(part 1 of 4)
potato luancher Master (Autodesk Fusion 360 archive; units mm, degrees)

design "potato luancher" references "Broached Hexagon Socket Head Cap Screw ANSI B18.3.1M - M3x0.5 x 25 Steel Grade 2 Zinc", "Socket Head Cap Screw JIS B 1176 - M3 x 0.5 x 20 Steel 4.6 Plain", "Hexagon Socket Head Cap Screw ANSI B18.3 - 1/4-28 UNF x 0.75 Steel Grade 2 Plain"
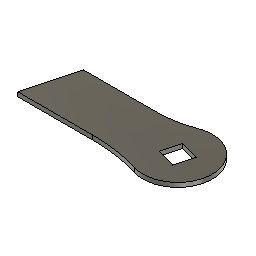
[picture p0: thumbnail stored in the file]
parameter "valveShaftHoleSzOffset" = 0.3
parameter "camInnerDiameter" = 80.9625 (= "3.1875 * 1 in")
parameter "big_nut" = 11.8872
parameter "d3" = 2.5
parameter "d71" = 3.175 (= "( 1 / 8 ) * 1 in")
parameter "d88" = 1.5189
parameter "d205" = 6.35
parameter "d237" = 2
parameter "d459" = 152.4
sketch "valve profile" plane through (0, 0, 0) normal (0, 1, 0) x axis (1, 0, 0)
canvas "Canvas1"
sketch "tank profile" plane through (0, 0, 0) normal (1, 0, 0) x axis (0, 1, 0)
  line L1 (0, 24.13) -> (-37.338, 24.13)
  line L2 (0, -24.13) -> (0, 24.13)
  line L3 (-37.338, -24.13) -> (0, -24.13)
  line L4 (-37.338, 24.13) -> (-37.338, -24.13)
  line L5 (146.556, 88.9) -> (44.956, 88.9)
  line L6 (146.556, -88.9) -> (146.556, 88.9)
  line L7 (44.956, -88.9) -> (146.556, -88.9)
  line L8 (44.956, 88.9) -> (44.956, -88.9)
  line L9 (-86.3742, 0) -> (44.956, 0)
  line L10 (146.556, 0) -> (-37.338, 0)
  arc A1 centre (69.1365, 24.13) radius 69.1365 clockwise from (0, 24.13) to (44.956, 88.9)
  arc A2 centre (69.1365, -24.13) radius 69.1365 clockwise from (44.956, -88.9) to (0, -24.13)
  point P11 (44.956, 0)
  point P13 (0, 0)
  point P3 (0, 24.13)
  point P16 (0, -24.13)
  point P6 (44.956, 88.9)
  point P15 (44.956, -88.9)
  point P17 (0, 0)
  point P18 (-37.338, 0)
  point P19 (146.556, 0)
  point P2 (-37.338, 24.13)
  point P5 (-37.338, -24.13)
  point P8 (146.556, 88.9)
  point P9 (146.556, -88.9)
  horizontal L1
  vertical L2
  horizontal L3
  vertical L4
  horizontal L5
  vertical L6
  horizontal L7
  vertical L8
  midpoint L8 P11
  perpendicular L8 L9
  midpoint L2 P13
  coincident L9 P13
  tangent L2 A1
  symmetric P3 L9 P16
  symmetric P6 L9 P15
  symmetric A1 L9 A2
  coincident P13 P17
  midpoint L4 P18
  midpoint L6 P19
  dimension "d4" distance P2 P5 = 48.26
  dimension "d5" distance P2 P3 = 37.338
  dimension "d6" distance P8 P9 = 177.8
  dimension "d7" distance P6 P8 = 101.6
  dimension "d8" distance L2 L8 = 44.956
  dimension "d320" AlongDistance = 263.274
  dimension "d458" diameter = 19.05
revolve "Revolve1" sketch "tank profile" AlongAngle 360
copy_paste_bodies "CutPasteBodies1"
sketch "Sketch1" plane through (0, 0, 0) normal (1, 0, 0) x axis (0, 1, 0)
  line L1 (-91.948, 28.067) -> (-77.216, 28.067)
  line L2 (-91.948, -28.067) -> (-91.948, 28.067)
  line L3 (-77.216, -28.067) -> (-91.948, -28.067)
  line L4 (-77.216, 28.067) -> (-77.216, -28.067)
  line L5 (-91.948, -28.067) -> (-77.216, 28.067)
  line L6 (-77.216, -28.067) -> (-91.948, 28.067)
  line L7 (-62.738, -31.115) -> (-28.702, -31.115)
  line L8 (-62.738, 31.115) -> (-62.738, -31.115)
  line L9 (-28.702, 31.115) -> (-62.738, 31.115)
  line L10 (-28.702, -31.115) -> (-28.702, 31.115)
  line L11 (-62.738, 31.115) -> (-28.702, -31.115)
  line L12 (-28.702, 31.115) -> (-62.738, -31.115)
  line L13 (-28.702, 32.385) -> (-14.224, 32.385)
  line L14 (-28.702, -32.385) -> (-28.702, 32.385)
  line L15 (-14.224, -32.385) -> (-28.702, -32.385)
  line L16 (-14.224, 32.385) -> (-14.224, -32.385)
  line L17 (-28.702, -32.385) -> (-14.224, 32.385)
  line L18 (-14.224, -32.385) -> (-28.702, 32.385)
  line L19 (-14.224, 27.9654) -> (0, 27.9654)
  line L20 (-14.224, -27.9654) -> (-14.224, 27.9654)
  line L21 (0, -27.9654) -> (-14.224, -27.9654)
  line L22 (0, 27.9654) -> (0, -27.9654)
  line L23 (-14.224, -27.9654) -> (0, 27.9654)
  line L24 (0, -27.9654) -> (-14.224, 27.9654)
  line L25 (27.6646, 0) -> (-172.9089, 0)
  arc A1 centre (-77.216, 63.9763) radius 35.9093 clockwise from (-62.738, 31.115) to (-77.216, 28.067)
  point P6 (-84.582, 0)
  point P11 (-45.72, 0)
  point P16 (-21.463, 0)
  point P21 (-7.112, 0)
  point P18 (-14.224, 27.9654)
  point P24 (0, 0)
  point P13 (-28.702, 32.385)
  point P1 (0, 0)
  point P2 (-77.216, 28.067)
  point P3 (-91.948, 28.067)
  point P9 (-62.738, 31.115)
  point P10 (-28.702, 31.115)
  point P12 (-14.224, 32.385)
  point P17 (0, 27.9654)
  point P4 (-91.948, -28.067)
  point P8 (-62.738, -31.115)
  point P14 (-28.702, -32.385)
  point P20 (0, -27.9654)
  horizontal L1
  perpendicular L1 L2
  parallel L1 L3
  parallel L2 L4
  coincident L5 P6
  coincident L6 P6
  horizontal L7
  perpendicular L7 L8
  parallel L7 L9
  parallel L8 L10
  coincident L11 P11
  coincident L12 P11
  horizontal L13
  perpendicular L13 L14
  parallel L13 L15
  parallel L14 L16
  coincident L17 P16
  coincident L18 P16
  horizontal L19
  perpendicular L19 L20
  parallel L19 L21
  parallel L20 L22
  coincident L23 P21
  coincident L24 P21
  coincident L16 P18
  perpendicular L2 L25
  coincident P6 L25
  coincident L25 P24
  coincident P11 L25
  coincident P16 L25
  coincident P21 L25
  coincident L10 P13
  coincident P1 L22
  tangent L1 A1
  dimension "d10" distance P2 P3 = 14.732
  dimension "d11" distance P9 P10 = 34.036
  dimension "d12" distance P12 P13 = 14.478
  dimension "d13" distance P17 P18 = 14.224
  dimension "d14" distance L2 L22 = 91.948
  dimension "d15" distance P3 P4 = 56.134
  dimension "d16" distance P8 P9 = 62.23
  dimension "d17" distance P13 P14 = 64.77
  dimension "d18" distance P17 P20 = 55.9308
revolve "Revolve1" sketch "Sketch1" AlongAngle 360
sketch "Sketch2" plane through (0, 0, 0) normal (1, 0, 0) x axis (0, 1, 0)
  line L1 (-33.782, 43.561) -> (-56.642, 43.561)
  line L2 (-33.782, 23.495) -> (-33.782, 43.561)
  line L3 (-56.642, 23.495) -> (-33.782, 23.495)
  line L4 (-56.642, 43.561) -> (-56.642, 23.495)
  line L5 (-62.738, 31.115) -> (-62.738, -31.115)
  line L6 (-28.702, 31.115) -> (-28.702, -31.115)
  line L7 (0, 27.9654) -> (0, -27.9654)
  line L8 (-62.738, 31.115) -> (-28.702, 31.115)
  line L9 (-45.212, 23.495) -> (-45.212, 43.561)
  line L10 (-45.212, 79.0444) -> (-45.212, 43.561)
  line L11 (-55.245, 43.561) -> (-35.179, 43.561)
  line L12 (-55.245, 47.117) -> (-55.245, 43.561)
  line L13 (-35.179, 47.117) -> (-55.245, 47.117)
  line L14 (-35.179, 43.561) -> (-35.179, 47.117)
  line L15 (-55.245, 47.117) -> (-35.179, 43.561)
  line L16 (-35.179, 47.117) -> (-55.245, 43.561)
  line L17 (-51.054, 47.117) -> (-39.37, 47.117)
  line L18 (-51.054, 58.547) -> (-51.054, 47.117)
  line L19 (-39.37, 58.547) -> (-51.054, 58.547)
  line L20 (-39.37, 47.117) -> (-39.37, 58.547)
  line L21 (-51.054, 58.547) -> (-39.37, 47.117)
  line L22 (-39.37, 58.547) -> (-51.054, 47.117)
  point P9 (-28.702, 31.115)
  point P12 (-28.702, 31.115)
  point P14 (-45.212, 43.561)
  point P15 (-45.212, 23.495)
  point P21 (-45.212, 45.339)
  point P17 (-35.179, 43.561)
  point P26 (-45.212, 52.832)
  point P22 (-39.37, 47.117)
  point P4 (-33.782, 23.495)
  point P2 (-56.642, 43.561)
  point P3 (-33.782, 43.561)
  point P19 (-55.245, 47.117)
  point P20 (-35.179, 47.117)
  point P24 (-51.054, 58.547)
  point P25 (-39.37, 58.547)
  horizontal L1
  vertical L2
  horizontal L3
  vertical L4
  coincident P9 P12
  perpendicular L5 L8
  midpoint L1 P14
  midpoint L3 P15
  perpendicular L1 L10
  horizontal L11
  perpendicular L11 L12
  parallel L11 L13
  parallel L12 L14
  coincident L15 P21
  coincident L16 P21
  coincident L10 P21
  coincident L1 P17
  horizontal L17
  perpendicular L17 L18
  parallel L17 L19
  parallel L18 L20
  coincident L21 P26
  coincident L22 P26
  coincident L10 P26
  coincident L13 P22
  dimension "d20" distance L2 L7 = 33.782
  dimension "d21" distance P4 L8 = 7.62
  dimension "d22" distance L1 L8 = 12.446
  dimension "d23" distance P2 P3 = 22.86
  dimension "d24" distance L1 L13 = 3.556
  dimension "d25" distance P19 P20 = 20.066
  dimension "d26" distance P24 P25 = 11.684
  dimension "d27" distance P22 P25 = 11.43
revolve "Revolve2" sketch "Sketch2" AlongAngle 360
sketch "Sketch3" plane through (0, 0, 58.547) normal (0, 0, 1) x axis (-1, 0, 0)
  line L1 (-3.429, 37.1067) -> (3.429, 37.1067)
  line L2 (-3.429, 53.3173) -> (-3.429, 37.1067)
  line L3 (3.429, 53.3173) -> (-3.429, 53.3173)
  line L4 (3.429, 37.1067) -> (3.429, 53.3173)
  line L5 (-3.429, 53.3173) -> (3.429, 37.1067)
  line L6 (3.429, 53.3173) -> (-3.429, 37.1067)
  circle C1 centre (0, 45.212) radius 5.842
  point P7 (0, 45.212)
  point P2 (0, 45.212)
  point P3 (3.429, 37.1067)
  point P6 (3.429, 53.3173)
  point P5 (-3.429, 53.3173)
  horizontal L1
  perpendicular L1 L2
  parallel L1 L3
  parallel L2 L4
  coincident L5 P7
  coincident L6 P7
  coincident P2 P7
  dimension "d29" distance P3 P6 = 16.2105
  dimension "d30" distance P5 P6 = 6.858
extrude "Extrude1" cut sketch "Sketch3" profile of C1 L2 L4 against normal blind 9.144
copy_paste_bodies "CutPasteBodies1"
sketch "Sketch1" plane through (0, 0, 49.403) normal (0, 0, 1) x axis (-1, 0, 0)
  line L1 (-3.429, 49.9418) -> (-3.429, 40.4822)
  line L2 (3.429, 49.9418) -> (3.429, 40.4822)
  line L3 (-3.429, 40.4822) -> (-3.429, 49.9418)
  line L4 (-10.795, 34.417) -> (10.795, 34.417)
  line L5 (-10.795, 56.007) -> (-10.795, 34.417)
  line L6 (10.795, 56.007) -> (-10.795, 56.007)
  line L7 (10.795, 34.417) -> (10.795, 56.007)
  line L8 (-10.795, 56.007) -> (10.795, 34.417)
  line L9 (10.795, 56.007) -> (-10.795, 34.417)
  arc A1 centre (0, 45.212) radius 5.842 clockwise from (-3.429, 40.4822) to (-3.429, 49.9418)
  arc A2 centre (0, 45.212) radius 5.842 clockwise from (-3.429, 49.9418) to (3.429, 49.9418)
  arc A3 centre (0, 45.212) radius 5.842 clockwise from (3.429, 40.4822) to (-3.429, 40.4822)
  circle C1 centre (0, 45.212) radius 10.795
  point P15 (0, 45.212)
  point P8 (0, 45.212)
  concentric A2 C1
  horizontal L4
  perpendicular L4 L5
  parallel L4 L6
  parallel L5 L7
  coincident L8 P15
  coincident L9 P15
  coincident P8 P15
  tangent C1 L7
  tangent C1 L4
  dimension "d33" diameter C1 = 21.59
extrude "Extrude1" new body sketch "Sketch1" profile of A1 L1 L2 A2 L3 A3 C1 L4 L5 L6 L7 along normal blind 3.175
copy_paste_bodies "CutPasteBodies1"
offset_faces "OffsetFaces1" distance 8.382 (= "-0.85 in + 1.18 in")
position "Position1"
as_built_joint "As-built1" OffsetX 0 OffsetY 0 OffsetZ 0 AngleZ 0
ground "Ground1"
work_plane "WorkPlane1" AlongDistance 44.958
extrude "Extrude1" add of existing geometry blind 330.2 (= "-4.00 in + 17 in")
sketch "plastic tank base" plane through (0, 476.756, 0) normal (0, 1, 0) x axis (-1, 0, 0)
  circle C1 centre (0, 0) radius 88.9
  circle C2 centre (0, 0) radius 90.4875
  concentric C1 C2
  dimension "d48" diameter C2 = 180.975
extrude "Extrude2" add sketch "plastic tank base" along normal blind 50.8
sketch "F handle shaft" plane through (0, 0, 0) normal (1, 0, 0) x axis (0, 1, 0)
  line L1 (70.356, 146.05) -> (83.056, 146.05)
  line L2 (70.356, 158.75) -> (70.356, 146.05)
  line L3 (83.056, 158.75) -> (70.356, 158.75)
  line L4 (83.056, 146.05) -> (83.056, 158.75)
  line L5 (70.356, 158.75) -> (83.056, 146.05)
  line L6 (83.056, 158.75) -> (70.356, 146.05)
  point P6 (76.706, 152.4)
  point P4 (70.356, 158.75)
  point P5 (83.056, 158.75)
  point P3 (70.356, 146.05)
  point P7 (44.956, 88.9)
  horizontal L1
  perpendicular L1 L2
  parallel L1 L3
  parallel L2 L4
  coincident L5 P6
  coincident L6 P6
  dimension "d51" distance P4 P5 = 12.7
  dimension "d52" distance P3 P4 = 12.7
  dimension "d53" distance P6 P7 = 63.5
  dimension "d54" distance P6 P7 = 31.75
extrude "Extrude1" new body sketch "F handle shaft" profile of L1 L2 L3 L4 distance 133.35
work_plane "WorkPlane3" AlongDistance -6.35 (= "-0.50 in / 2")
sketch "Sketch11" plane through (0, 76.706, 0) normal (0, -1, 0) x axis (-1, 0, 0)
  line L1 (-66.675, -146.05) -> (-66.675, -158.75)
  line L2 (-66.675, -158.75) -> (-66.675, -146.05)
  line L3 (-66.675, -146.05) -> (66.675, -146.05)
  line L4 (-66.675, -158.75) -> (-66.675, -146.05)
  line L5 (66.675, -158.75) -> (-66.675, -158.75)
  line L6 (66.675, -146.05) -> (66.675, -158.75)
  line L7 (-63.5, -62.217) -> (-63.5, -146.05)
  circle C1 centre (0, 0) radius 88.9
  circle C2 centre (0, 0) radius 88.9
  point P9 (-63.5, -146.05)
  point P10 (-63.5, -62.217)
  point P4 (-66.675, -146.05)
  coincident L3 P9
  vertical L7
  coincident C1 P10
  dimension "d66" distance P4 L7 = 3.175
work_plane "WorkPlane5" AlongDistance -3.175
sketch "f handle riser" plane through (63.5, 0, 0) normal (1, 0, 0) x axis (0, 1, 0)
  line L1 (83.056, 146.05) -> (70.356, 158.75)
  line L2 (81.1484, 62.217) -> (62.6534, 131.2414)
  line L3 (120.5924, 62.217) -> (81.1484, 62.217)
  line L4 (99.4551, 141.1024) -> (120.5924, 62.217)
  line L5 (90.9623, 99.1945) -> (76.706, 152.4)
  line L6 (71.9009, 96.7292) -> (110.0238, 101.6597)
  line L7 (76.706, 62.217) -> (76.706, 146.05)
  line L8 (70.356, 158.75) -> (83.056, 158.75)
  line L9 (70.356, 146.05) -> (70.356, 158.75)
  line L10 (83.056, 146.05) -> (70.356, 146.05)
  line L11 (83.056, 158.75) -> (83.056, 146.05)
  line L12 (69.594, 145.288) -> (69.594, 159.512)
  line L13 (83.818, 145.288) -> (69.594, 145.288)
  line L14 (83.818, 159.512) -> (83.818, 145.288)
  line L15 (69.594, 159.512) -> (83.818, 159.512)
  circle C1 centre (76.706, 152.4) radius 15.0812
  circle C2 centre (76.706, 152.4) radius 25.4
  point P4 (76.706, 152.4)
  point P6 (76.706, 152.4)
  point P5 (76.706, 152.4)
  point P7 (62.6534, 131.2414)
  point P10 (99.4551, 141.1024)
  point P11 (76.706, 152.4)
  point P13 (110.0238, 101.6597)
  point P14 (71.9009, 96.7292)
  point P12 (90.9623, 99.1945)
  point P15 (76.706, 62.217)
  point P3 (83.056, 146.05)
  point P16 (83.056, 146.05)
  point P2 (70.356, 158.75)
  point P17 (70.356, 158.75)
  midpoint L1 P4
  coincident P4 P6
  coincident P4 P5
  coincident C2 P7
  horizontal L3
  coincident C2 P10
  parallel L2 L4
  coincident P4 P11
  midpoint L4 P13
  midpoint L2 P14
  midpoint P12 L6
  parallel L4 L5
  coincident L3 P15
  coincident P3 P16
  coincident P2 P17
  dimension "d59" diameter C1 = 30.1625 (= "1 in + ( 3 / 16 ) * 1 in")
  dimension "d60" diameter C2 = 50.8
  dimension "d64" distance L2 L4 = 38.1
  dimension "d69" angle L2 L7 = 15
  dimension "d70" = 0.762
face "Face1" sketch "f handle riser"
copy_paste "CutPaste"
fillet "Fillet1" radius 76.2 125.73
mirror_component "MirrorComponent1"
derived_instance "DerivedInstance1"
sketch "Sketch5" plane through (0, 0, 43.561) normal (0, 0, 1) x axis (-1, 0, 0)
  line L1 (0, 111.0784) -> (0, -6.2651)
  line L2 (2.9845, 62.7225) -> (-2.9845, 62.7225)
  line L3 (2.9845, 56.2455) -> (2.9845, 62.7225)
  line L4 (-2.9845, 56.2455) -> (2.9845, 56.2455)
  line L5 (-2.9845, 62.7225) -> (-2.9845, 56.2455)
  line L6 (2.9845, 56.2455) -> (-2.9845, 62.7225)
  line L7 (-2.9845, 56.2455) -> (2.9845, 62.7225)
  circle C1 centre (0, 45.212) radius 10.033
  circle C2 centre (0, 45.212) radius 11.43
  point P1 (0, 0)
  point P9 (0, 59.484)
  point P7 (2.9845, 56.2455)
  point P5 (-2.9845, 62.7225)
  point P6 (2.9845, 62.7225)
  point P8 (-2.9845, 56.2455)
  vertical L1
  coincident P1 L1
  horizontal L2
  perpendicular L2 L3
  parallel L2 L4
  parallel L3 L5
  coincident L6 P9
  coincident L7 P9
  coincident L1 P9
  coincident C2 P7
  dimension "d80" distance P5 P6 = 5.969
  dimension "d81" distance P5 P8 = 6.477
extrude "Extrude2" add sketch "Sketch5" profile of C2 L2 L3 L5 against normal blind 13.208
sketch "Sketch1" plane through (0, 0, 49.403) normal (0, 0, 1) x axis (-1, 0, 0)
  line L1 (3.429, 40.4822) -> (3.429, 49.9418)
  line L2 (3.429, 49.9418) -> (3.429, 40.4822)
  line L3 (-3.429, 40.4822) -> (-3.429, 49.9418)
  line L4 (-3.429, 49.9418) -> (-3.429, 40.4822)
  line L5 (-3.729, 40.3316) -> (-3.729, 50.0924)
  line L6 (3.729, 50.0924) -> (3.729, 40.3316)
  arc A1 centre (0, 45.212) radius 5.842 clockwise from (3.429, 49.9418) to (3.429, 40.4822)
  arc A2 centre (0, 45.212) radius 5.842 clockwise from (-3.429, 49.9418) to (3.429, 49.9418)
  arc A3 centre (0, 45.212) radius 5.842 clockwise from (3.429, 40.4822) to (-3.429, 40.4822)
  arc A4 centre (0, 45.212) radius 5.842 clockwise from (-3.429, 40.4822) to (-3.429, 49.9418)
  arc A5 centre (0, 45.212) radius 6.142 clockwise from (-3.729, 50.0924) to (3.729, 50.0924)
  arc A6 centre (0, 45.212) radius 6.142 clockwise from (3.729, 40.3316) to (-3.729, 40.3316)
  circle C1 centre (0, 45.212) radius 40.4812
  concentric A2 C1
  dimension "d84" = 0.3 (= "valveShaftHoleSzOffset")
  dimension "d86" diameter C1 = 80.9625 (= "camInnerDiameter")
face "Face1" sketch "Sketch1"
sketch "Sketch2" plane through (0, 0, 52.578) normal (0, 0, 1) x axis (-1, 0, 0)
  line L1 (3.729, 40.3316) -> (3.729, 50.0924)
  line L2 (-3.729, 50.0924) -> (-3.729, 40.3316)
  arc A1 centre (0, 45.212) radius 6.142 clockwise from (3.729, 40.3316) to (-3.729, 40.3316)
  arc A2 centre (0, 45.212) radius 6.142 clockwise from (-3.729, 50.0924) to (3.729, 50.0924)
  circle C1 centre (0, 45.212) radius 40.4812
  circle C2 centre (0, 45.212) radius 20.1612
  dimension "d89" = -20.32
extrude "Extrude1" new body sketch "Sketch2" profile of C1 C2 along normal blind 7.62
sketch "Sketch3" plane through (0, 0, 60.198) normal (0, 0, 1) x axis (-1, 0, 0)
  circle C1 centre (0, 45.212) radius 20.1612
  circle C2 centre (0, 45.212) radius 40.4812
face "Face1" sketch "Sketch3"
as_built_joint "As-built1"
as_built_joint "As-built2"
sketch "Sketch4" plane through (0, 0, 61.7169) normal (0, 0, 1) x axis (-1, 0, 0)
  line L1 (0, 0) -> (0, 14.8908)
  circle C1 centre (0, 45.212) radius 20.1612
  circle C2 centre (0, 45.212) radius 40.4812
  circle C3 centre (0, 45.212) radius 30.3212
  circle C4 centre (0, 14.8908) radius 1.61
  circle C5 centre (23.7061, 26.307) radius 1.61
  circle C6 centre (29.561, 51.9591) radius 1.61
  circle C7 centre (13.1559, 72.5305) radius 1.61
  circle C8 centre (-13.1559, 72.5305) radius 1.61
  circle C9 centre (-29.561, 51.9591) radius 1.61
  circle C10 centre (-23.7061, 26.307) radius 1.61
  point P4 (0, 14.8908)
  point P5 (0, 14.8908)
  point P1 (0, 0)
  point P6 (0, 0)
  coincident C3 P4
  coincident P4 P5
  coincident P1 P6
  vertical L1
  dimension "d92" = -10.16
  dimension "d93" diameter C4 = 3.22
  dimension "d95" C-Pattern1-Angle = 360
extrude "Extrude1" cut sketch "Sketch4" profile of C4 C5 C6 C7 C8 C9 C10 against normal blind 10.668
extrude "Extrude3" cut of existing geometry blind -1.651
step "Screw1"
joint "Assemble1" alignAngle 0 alignOffsetX 0 alignOffsetY 0 alignOffsetZ 0
step "Screw2"
joint "Assemble2" alignAngle 0 alignOffsetX 0 alignOffsetY 0 alignOffsetZ 0
step "Screw3"
joint "Assemble3" alignAngle 0 alignOffsetX 0 alignOffsetY 0 alignOffsetZ 0
step "Screw4"
joint "Assemble4" alignAngle 0 alignOffsetX 0 alignOffsetY 0 alignOffsetZ 0
step "Screw5"
joint "Assemble5" alignAngle 0 alignOffsetX 0 alignOffsetY 0 alignOffsetZ 0
step "Screw6"
joint "Assemble6" alignAngle 0 alignOffsetX 0 alignOffsetY 0 alignOffsetZ 0
step "Screw7"
joint "Assemble7" alignAngle 0 alignOffsetX 0 alignOffsetY 0 alignOffsetZ 0
sketch "Sketch5" plane through (0, 0, 0) normal (1, 0, 0) x axis (0, 1, 0)
  line L1 (-85.6932, 60.198) -> (-4.7307, 60.198)
  line L2 (-85.6932, 52.578) -> (-4.7307, 52.578)
  line L3 (-85.6932, 52.578) -> (-85.6932, 60.198)
  line L4 (-60.0977, 56.388) -> (-85.6932, 56.388)
  line L5 (-80.0118, 40.5392) -> (-80.0118, 63.1735)
  line L6 (-81.7745, 58.4607) -> (-85.6932, 59.0986)
  line L7 (-81.7745, 54.3153) -> (-85.6932, 53.6774)
  line L8 (-45.212, 74.0345) -> (-45.212, 60.198)
  line L9 (-73.994, 36.9631) -> (-71.067, 36.9631)
  line L10 (-71.067, 61.7169) -> (-73.994, 61.7169)
  circle C1 centre (-82.1118, 56.388) radius 2.1
  point P3 (-85.6932, 60.198)
  point P7 (-85.6932, 60.198)
  point P5 (-85.6932, 52.578)
  point P8 (-85.6932, 52.578)
  point P9 (-85.6932, 56.388)
  point P6 (-82.1118, 56.388)
  point P13 (-85.6932, 59.0986)
  point P14 (-81.7745, 58.4607)
  point P15 (-85.6932, 53.6774)
  point P16 (-81.7745, 54.3153)
  point P17 (-45.212, 60.198)
  coincident P3 P7
  coincident P5 P8
  midpoint L3 P9
  perpendicular L3 L4
  coincident P6 L4
  perpendicular L4 L5
  tangent C1 L5
  coincident L3 P13
  coincident C1 P14
  tangent C1 L6
  symmetric L4 P13 P15
  symmetric L4 P14 P16
  midpoint L1 P17
  perpendicular L1 L8
  dimension "d130" diameter C1 = 4.2
  dimension "d132" distance P7 P13 = 1.0994
  dimension "d227" distance P7 P8 = 7.62
  dimension "d228" distance P6 L3 = 3.5814
revolve "Revolve1" sketch "Sketch5" AlongAngle 360
as_built_joint "As-built2" OffsetX 0 OffsetY 0 OffsetZ 0 AngleZ 0
work_plane "WorkPlane7"
sketch "Sketch12" plane through (0, 0, 56.388) normal (0, 0, 1) x axis (-1, 0, 0)
  line L1 (0, 128.6036) -> (0, 68.326)
  line L2 (8.6873, 81.0039) -> (0, 104.8721)
  circle C1 centre (13.1559, 95.6445) radius 1.61
  circle C2 centre (0, 38.0048) radius 1.61
  circle C3 centre (-13.1559, 95.6445) radius 1.61
  circle C4 centre (29.561, 75.0731) radius 1.61
  circle C5 centre (-23.7061, 49.421) radius 1.61
  circle C6 centre (-29.561, 75.0731) radius 1.61
  circle C7 centre (23.7061, 49.421) radius 1.61
  circle C8 centre (0, 68.326) radius 20.1612
  circle C9 centre (0, 68.326) radius 40.4812
  circle C10 centre (0, 68.326) radius 36.5461
  circle C11 centre (0, 68.326) radius 36.5461
  point P9 (0, 68.326)
  point P11 (0, 68.326)
  point P13 (0, 104.8721)
  point P14 (8.6873, 81.0039)
  coincident P9 P11
  vertical L1
  coincident L1 P13
  coincident C10 P13
  dimension "d138" angle L1 L2 = 20
  dimension "d139" distance P13 P14 = 25.4
pipe "Pipe1" SectionSize 4.2 SectionThickness 1.0414
extrude "Extrude2" new body sketch "f handle riser" profile of C1 L14 L15 L13 L12 against normal blind 127
sketch "Sketch13" plane through (0, 0, 0) normal (0, 1, 0) x axis (1, 0, 0)
  line L1 (63.5, -145.288) -> (63.5, -159.512)
  line L2 (63.5, -159.512) -> (63.5, -145.288)
  line L3 (63.5, -62.217) -> (63.5, -115.4598)
  line L4 (63.5, -113.3189) -> (63.5, -62.217)
  line L5 (63.5, -137.6992) -> (63.5, -113.3189)
  line L6 (63.5, -137.6992) -> (63.5, -177.8)
  line L7 (63.5, -151.6607) -> (63.5, -115.4598)
  circle C1 centre (0, 0) radius 24.13
  circle C2 centre (0, 0) radius 88.9
  circle C3 centre (49.8574, -89.6059) radius 10.6426
  circle C4 centre (49.8574, -89.6059) radius 13.6426
  tangent L4 C4
  tangent C2 C4
  dimension "d147" diameter C3 = 21.2852
  dimension "d149" = 3
work_plane "WorkPlane8" AlongDistance 107.95
extrude "Extrude1" sketch "Sketch13" profile of C3 C4 blind 342.9 second side blind 38.1
sketch "Sketch14" plane through (0, 69.85, 0) normal (0, -1, 0) x axis (1, 0, 0)
  line L1 (30.7907, 83.3975) -> (37.9359, 96.2391)
  line L2 (54.6337, 70.1311) -> (61.7789, 82.9727)
  line L3 (61.7789, 82.9727) -> (37.9359, 96.2391)
  circle C1 centre (49.8574, 89.6059) radius 10.6426
  circle C2 centre (49.8574, 89.6059) radius 13.6426
  circle C3 centre (0, 0) radius 24.13
  circle C4 centre (0, 0) radius 88.9
  point P4 (37.9359, 96.2391)
  point P5 (30.7907, 83.3975)
  point P6 (61.7789, 82.9727)
  point P7 (54.6337, 70.1311)
  coincident C2 P4
  coincident C4 P5
  coincident C2 P6
  coincident C4 P7
  perpendicular L1 L3
  perpendicular L2 L3
  tangent C2 L1
  equal L1 L2
extrude "Extrude2" add sketch "Sketch14" profile of C2 C4 L1 L2 against normal blind 50.8
work_plane "WorkPlane9"
mirror "Mirror1" mirrorStitchTolerance 0.1016
sketch "Sketch6" plane through (0, 0, 49.403) normal (0, 0, -1) x axis (1, 0, 0)
  line L1 (-3.729, 50.0924) -> (-3.729, 40.3316)
  line L2 (3.729, 40.3316) -> (3.729, 50.0924)
  curve K1 (2.9845, 56.2455) -> (-11.43, 45.212)
  curve K2 (-11.43, 45.212) -> (-2.9845, 56.2455)
  line L3 (2.9845, 56.2455) -> (2.9845, 62.7225)
  line L4 (2.9845, 62.7225) -> (2.9845, 56.2455)
  line L5 (-2.9845, 62.7225) -> (2.9845, 62.7225)
  line L6 (-2.9845, 62.7225) -> (2.9845, 62.7225)
  line L7 (-2.9845, 62.7225) -> (-2.9845, 56.2455)
  line L8 (-2.9845, 56.2455) -> (-2.9845, 62.7225)
  line L9 (-3.2845, 61.8652) -> (-13.4445, 61.8652)
  line L10 (-3.2845, 57.1027) -> (-3.2845, 61.8652)
  line L11 (-13.4445, 57.1027) -> (-3.2845, 57.1027)
  line L12 (-13.4445, 61.8652) -> (-13.4445, 57.1027)
  line L13 (0, 83.1244) -> (0, 45.212)
  line L14 (2.9845, 59.484) -> (-2.9845, 59.484)
  line L15 (-13.7445, 56.8027) -> (-2.9845, 56.8027)
  line L16 (-13.7445, 62.1652) -> (-13.7445, 56.8027)
  line L17 (-2.9845, 62.1652) -> (-13.7445, 62.1652)
  line L18 (-2.9845, 56.8027) -> (-2.9845, 62.1652)
  line L19 (13.4445, 61.8652) -> (3.2845, 61.8652)
  line L20 (13.4445, 57.1027) -> (13.4445, 61.8652)
  line L21 (3.2845, 57.1027) -> (13.4445, 57.1027)
  line L22 (3.2845, 61.8652) -> (3.2845, 57.1027)
  line L23 (2.9845, 56.8027) -> (13.7445, 56.8027)
  line L24 (2.9845, 62.1652) -> (2.9845, 56.8027)
  line L25 (13.7445, 62.1652) -> (2.9845, 62.1652)
  line L26 (13.7445, 56.8027) -> (13.7445, 62.1652)
  line L27 (11.8907, 31.7675) -> (16.6532, 31.7675)
  line L28 (16.6532, 41.9275) -> (11.8907, 41.9275)
  line L29 (16.6532, 31.7675) -> (16.6532, 41.9275)
  line L30 (16.9532, 31.4675) -> (16.9532, 42.2275)
  line L31 (11.5907, 31.4675) -> (16.9532, 31.4675)
  line L32 (11.8907, 41.9275) -> (11.8907, 31.7675)
  line L33 (11.5907, 42.2275) -> (11.5907, 31.4675)
  line L34 (16.9532, 42.2275) -> (11.5907, 42.2275)
  line L35 (6.3219, 45.212) -> (0, 45.212)
  arc A1 centre (0, 45.212) radius 6.142 clockwise from (-3.729, 50.0924) to (3.729, 50.0924)
  arc A2 centre (0, 45.212) radius 6.142 clockwise from (3.729, 40.3316) to (-3.729, 40.3316)
  circle C1 centre (0, 45.212) radius 40.4812
  arc A3 centre (0, 45.212) radius 11.43 clockwise from (2.9845, 56.2455) to (-2.9845, 56.2455)
  circle C2 centre (0, 14.8908) radius 1.61
  circle C3 centre (-29.561, 51.9591) radius 1.61
  circle C4 centre (13.1559, 72.5305) radius 1.61
  circle C5 centre (29.561, 51.9591) radius 1.61
  circle C6 centre (-13.1559, 72.5305) radius 1.61
  circle C7 centre (-23.7061, 26.307) radius 1.61
  circle C8 centre (23.7061, 26.307) radius 1.61
  point P9 (0, 45.212)
  point P22 (0, 45.212)
  point P24 (-2.9845, 59.484)
  point P25 (2.9845, 59.484)
  point P26 (-13.4445, 59.484)
  point P30 (-2.9845, 62.1652)
  point P35 (13.4445, 59.484)
  point P38 (2.9845, 62.1652)
  point P49 (14.272, 31.7675)
  point P50 (0, 45.212)
  point P44 (14.272, 42.2275)
  point P18 (-13.4445, 61.8652)
  point P21 (-13.4445, 57.1027)
  point P19 (-3.2845, 61.8652)
  point P31 (3.2845, 61.8652)
  point P34 (3.2845, 57.1027)
  point P32 (13.4445, 61.8652)
  point P46 (16.6532, 41.9275)
  point P48 (11.8907, 41.9275)
  point P47 (16.6532, 31.7675)
  horizontal L9
  vertical L10
  horizontal L11
  vertical L12
  coincident P9 P22
  vertical L13
  midpoint L8 P24
  midpoint L4 P25
  midpoint L12 P26
  coincident L14 P26
  coincident L8 P30
  horizontal L19
  vertical L20
  horizontal L21
  vertical L22
  midpoint L20 P35
  coincident L14 P35
  coincident L4 P38
  midpoint P49 L27
  coincident P9 P50
  perpendicular L13 L35
  perpendicular L28 L29
  perpendicular L27 L32
  perpendicular L28 L32
  coincident P44 L34
  midpoint P44 L34
  dimension "d160" distance P18 P21 = 4.7625 (= "( 3 / 16 ) * 1 in")
  dimension "d161" distance P18 P19 = 10.16
  dimension "d162" = -0.3
  dimension "d163" distance P31 P34 = 4.7625 (= "d160")
  dimension "d164" distance P31 P32 = 10.16 (= "d161")
  dimension "d165" = -0.3
  dimension "d167" distance P46 P48 = 4.7625 (= "d160")
  dimension "d168" distance P46 P47 = 10.16 (= "d161")
  dimension "d169" distance L13 L24 = 2.9845
  dimension "d170" distance L34 L35 = 2.9845 (= "d169")
  dimension "d171" distance P22 L23 = 11.5907
  dimension "d172" distance P9 L33 = 11.5907 (= "d171")
extrude "Extrude2" cut sketch "Sketch6" profile of L7 L8 L9 L10 L11 L12 L17 L18 L16 L15 L27 L28 L29 L32 L30 L31 L33 L34 against normal blind 3.175
sketch "buffer tube anchor face" plane through (0, 450.85, 0) normal (0, 1, 0) x axis (-1, 0, 0)
  line L1 (-54.6337, 70.1311) -> (-61.7789, 82.9727)
  line L2 (-37.9359, 96.2391) -> (-30.7907, 83.3975)
  line L3 (0, 0) -> (-51.4011, 92.3804)
  line L4 (-58.7025, 66.7625) -> (-51.4011, 92.3804)
  line L5 (-25.7832, 85.079) -> (-51.4011, 92.3804)
  circle C1 centre (-49.8574, 89.6059) radius 10.6426
  arc A1 centre (-49.8574, 89.6059) radius 13.6426 clockwise from (-61.7789, 82.9727) to (-37.9359, 96.2391)
  arc A2 centre (0, 0) radius 88.9 clockwise from (-54.6337, 70.1311) to (-30.7907, 83.3975)
  circle C2 centre (0, 0) radius 88.9
  point P7 (0, 0)
  point P9 (0, 0)
  point P2 (-49.8574, 89.6059)
  point P12 (0, 0)
  point P6 (-30.7907, 83.3975)
  point P11 (-25.7832, 85.079)
  point P10 (-58.7025, 66.7625)
  point P8 (-51.4011, 92.3804)
  coincident P7 P9
  coincident P2 L3
  coincident P9 P12
  coincident P6 C2
  coincident P11 C2
  coincident P10 C2
  perpendicular L4 L5
  equal L4 L5
  dimension "d175" distance P2 P8 = 3.175
work_plane "WorkPlane10" sketch "buffer tube anchor face" AlongDistance 25.4
sketch "archor tail" plane through (0, 476.25, 0) normal (0, 1, 0) x axis (1, 0, 0)
  line L1 (54.6337, -70.1311) -> (61.7789, -82.9727)
  line L2 (37.9359, -96.2391) -> (30.7907, -83.3975)
  circle C1 centre (49.8574, -89.6059) radius 10.6426
  arc A1 centre (49.8574, -89.6059) radius 13.6426 clockwise from (61.7789, -82.9727) to (37.9359, -96.2391)
  arc A2 centre (0, 0) radius 88.9 clockwise from (54.6337, -70.1311) to (30.7907, -83.3975)
  point P9 (43.2242, -77.6845)
  midpoint A2 P9
sketch "Sketch1" plane through (0, 260.35, 0) normal (0, 1, 0) x axis (1, 0, 0)
  line L1 (54.6337, -70.1311) -> (61.7789, -82.9727)
  line L2 (37.9359, -96.2391) -> (30.7907, -83.3975)
  line L3 (0, 0) -> (49.8574, -89.6059)
  line L4 (23.7839, -85.6594) -> (41.1317, -100.0932)
  line L5 (49.8574, -89.6059) -> (23.7839, -85.6594)
  line L6 (36.3684, -87.5642) -> (23.7839, -85.6594)
  line L7 (32.0777, -86.9148) -> (29.3021, -90.2507)
  line L8 (36.3684, -87.5642) -> (32.0777, -86.9148)
  line L9 (60.2497, -65.3696) -> (63.369, -87.7202)
  line L10 (61.7789, -82.9727) -> (54.6337, -70.1311)
  line L11 (30.7907, -83.3975) -> (37.9359, -96.2391)
  circle C1 centre (49.8574, -89.6059) radius 10.6426
  arc A1 centre (49.8574, -89.6059) radius 13.6426 clockwise from (61.7789, -82.9727) to (37.9359, -96.2391)
  arc A2 centre (0, 0) radius 88.9 clockwise from (54.6337, -70.1311) to (30.7907, -83.3975)
  circle C2 centre (32.0777, -86.9148) radius 1.75
  circle C3 centre (32.0777, -86.9148) radius 2.75
  circle C4 centre (0, 0) radius 88.9
  arc A3 centre (49.8574, -89.6059) radius 13.6426 clockwise from (37.9359, -96.2391) to (43.2242, -77.6845)
  circle C5 centre (56.944, -73.079) radius 1.75
  circle C6 centre (49.8574, -89.6059) radius 10.6426
  arc A4 centre (0, 0) radius 88.9 clockwise from (54.6337, -70.1311) to (30.7907, -83.3975)
  arc A5 centre (49.8574, -89.6059) radius 13.6426 clockwise from (61.7789, -82.9727) to (37.9359, -96.2391)
  point P2 (49.8574, -89.6059)
  point P9 (49.8574, -89.6059)
  point P7 (0, 0)
  point P10 (0, 0)
  point P6 (30.7907, -83.3975)
  point P12 (54.6337, -70.1311)
  point P15 (0, 0)
  point P16 (41.1317, -100.0932)
  point P17 (23.7839, -85.6594)
  point P18 (36.3684, -87.5642)
  point P11 (32.0777, -86.9148)
  point P22 (29.3021, -90.2507)
  point P8 (32.0777, -86.9148)
  point P23 (32.0777, -86.9148)
  point P24 (32.0777, -86.9148)
  point P25 (63.369, -87.7202)
  point P26 (60.2497, -65.3696)
  coincident P2 P9
  coincident P7 P10
  concentric C2 C3
  symmetric P6 L3 P12
  coincident P10 P15
  coincident P6 C4
  coincident A1 P16
  coincident C4 P17
  tangent A1 L4
  coincident L5 P18
  coincident P18 A3
  coincident P11 L6
  coincident L4 P22
  coincident P8 P23
  perpendicular L4 L7
  coincident P8 P24
  parallel L5 L8
  equal L7 L8
  symmetric C2 L3 C5
  symmetric L3 P16 P25
  symmetric L3 P17 P26
  dimension "d180" diameter C2 = 3.5
  dimension "d181" diameter C3 = 5.5
  dimension "d182" distance P17 P18 = 12.7279
extrude "Extrude3" add sketch "Sketch1" profile of C1 A1 L1 A2 L2 C2 C3 C4 L4 L6 A3 L7 L8 L9 C5 C6 A4 L10 A5 L11 distance 16
sketch "Sketch2" plane through (0, 252.35, 0) normal (0, -1, 0) x axis (1, 0, 0)
  line L1 (23.7839, 85.6594) -> (41.1317, 100.0932)
  line L2 (34.6526, 89.0557) -> (35.2192, 85.7553)
  line L3 (31.5111, 90.2151) -> (34.6526, 89.0557)
  line L4 (28.9362, 88.0742) -> (31.5111, 90.2151)
  line L5 (29.5029, 84.7739) -> (28.9362, 88.0742)
  line L6 (32.6444, 83.6144) -> (29.5029, 84.7739)
  line L7 (35.2192, 85.7553) -> (32.6444, 83.6144)
  line L8 (31.0736, 84.1942) -> (32.0777, 86.9148)
  line L9 (0, 0) -> (31.0736, 84.1942)
  line L10 (0, 0) -> (49.8574, 89.6059)
  line L11 (60.0472, 74.3374) -> (57.4058, 76.3956)
  line L12 (59.5854, 71.0208) -> (60.0472, 74.3374)
  line L13 (57.4058, 76.3956) -> (54.3026, 75.1372)
  line L14 (54.3026, 75.1372) -> (53.8408, 71.8206)
  line L15 (56.4822, 69.7623) -> (59.5854, 71.0208)
  line L16 (55.1615, 70.7915) -> (56.944, 73.079)
  line L17 (53.8408, 71.8206) -> (56.4822, 69.7623)
  arc A1 centre (49.8574, 89.6059) radius 13.6426 clockwise from (43.2242, 77.6845) to (41.1317, 100.0932)
  arc A2 centre (0, 0) radius 88.9 clockwise from (23.7839, 85.6594) to (43.2242, 77.6845)
  circle C1 centre (32.0777, 86.9148) radius 1.75
  circle C2 centre (56.944, 73.079) radius 1.75
  point P7 (32.0777, 86.9148)
  point P14 (32.0777, 86.9148)
  point P15 (32.0777, 86.9148)
  point P16 (31.0736, 84.1942)
  point P17 (0, 0)
  point P18 (0, 0)
  point P5 (23.7839, 85.6594)
  point P22 (60.2497, 65.3696)
  point P8 (35.2192, 85.7553)
  point P31 (54.3026, 75.1372)
  point P9 (34.6526, 89.0557)
  point P24 (57.4058, 76.3956)
  point P10 (31.5111, 90.2151)
  point P25 (60.0472, 74.3374)
  point P11 (28.9362, 88.0742)
  point P26 (59.5854, 71.0208)
  point P12 (29.5029, 84.7739)
  point P27 (56.4822, 69.7623)
  point P13 (32.6444, 83.6144)
  point P28 (53.8408, 71.8206)
  point P21 (56.944, 73.079)
  point P29 (56.944, 73.079)
  point P23 (55.1615, 70.7915)
  coincident P7 P14
  coincident P14 P15
  midpoint L6 P16
  parallel L8 L9
  coincident P17 P18
  symmetric P5 L10 P22
  symmetric C1 L10 C2
  symmetric P8 L10 P31
  symmetric P9 L10 P24
  symmetric P10 L10 P25
  symmetric P11 L10 P26
  symmetric P12 L10 P27
  symmetric P13 L10 P28
  symmetric P14 L10 P21
  symmetric P15 L10 P29
  symmetric P16 L10 P23
  dimension "d185" distance P14 L7 = 2.9 (= "( ( 5.5 + 0.3 ) / 2 ) * 1 mm")
extrude "Extrude4" cut sketch "Sketch2" profile of C1 L2 L3 L4 L5 L6 L7 C2 L11 L12 L13 L14 L15 L17 against normal blind 1.75
split "Split1"
step "Screw1"
joint "Assemble1" alignAngle 0 alignOffsetX 0 alignOffsetY 0 alignOffsetZ 0
step "Screw2"
joint "Assemble2" alignAngle 0 alignOffsetX 0 alignOffsetY 0 alignOffsetZ 0
work_plane "WorkPlane1"
sketch "Sketch3" plane through (42.7122, 0, 76.7643) normal (0.4862, 0, 0.8738) x axis (0, 1, 0)
  line L1 (260.35, 12.7239) -> (260.35, -12.7239)
  line L2 (252.35, 12.7239) -> (260.35, 12.7239)
  line L3 (252.35, 0) -> (252.35, 13.6426)
  line L4 (252.35, -13.6426) -> (252.35, 0)
  line L5 (260.35, -12.7239) -> (252.35, -12.7239)
  line L6 (69.85, 13.6426) -> (120.65, 13.6426)
  line L7 (69.85, -13.6426) -> (69.85, 13.6426)
  line L8 (120.65, -13.6426) -> (69.85, -13.6426)
  line L9 (120.65, 0) -> (120.65, -13.6426)
  line L10 (120.65, 13.6426) -> (120.65, 0)
  line L11 (260.35, 12.7239) -> (260.35, -12.7239)
  line L12 (268.35, -12.7239) -> (260.35, -12.7239)
  line L13 (268.35, 0) -> (268.35, -13.6426)
  line L14 (268.35, 13.6426) -> (268.35, 0)
  line L15 (260.35, 12.7239) -> (268.35, 12.7239)
  line L16 (400.05, 13.6426) -> (450.85, 13.6426)
  line L17 (400.05, 0) -> (400.05, 13.6426)
  line L18 (400.05, -13.6426) -> (400.05, 0)
  line L19 (450.85, -13.6426) -> (400.05, -13.6426)
  line L20 (450.85, 13.6426) -> (450.85, -13.6426)
  line L21 (400.05, 0) -> (120.65, 0)
  line L22 (120.65, 0) -> (252.35, 0)
  line L23 (154.75, 1.75) -> (218.25, 1.75)
  line L24 (218.25, -1.75) -> (154.75, -1.75)
  line L25 (154.75, 0) -> (218.25, 0)
  line L26 (302.45, -1.75) -> (365.95, -1.75)
  line L27 (365.95, 0) -> (302.45, 0)
  line L28 (365.95, 1.75) -> (302.45, 1.75)
  arc A1 centre (154.75, 0) radius 1.75 clockwise from (154.75, -1.75) to (154.75, 1.75)
  arc A2 centre (218.25, 0) radius 1.75 clockwise from (218.25, 1.75) to (218.25, -1.75)
  arc A3 centre (302.45, 0) radius 1.75 clockwise from (302.45, -1.75) to (302.45, 1.75)
  arc A4 centre (365.95, 0) radius 1.75 clockwise from (365.95, 1.75) to (365.95, -1.75)
  point P13 (120.65, 0)
  point P26 (120.65, 0)
  point P23 (400.05, 0)
  point P27 (400.05, 0)
  point P6 (252.35, 0)
  point P28 (252.35, 0)
  point P34 (154.75, 0)
  point P35 (186.5, 0)
  point P29 (218.25, 1.75)
  point P38 (302.45, 1.75)
  point P30 (154.75, 1.75)
  point P36 (365.95, 1.75)
  point P31 (154.75, -1.75)
  point P39 (365.95, -1.75)
  point P32 (218.25, -1.75)
  point P42 (302.45, -1.75)
  point P40 (334.2, 0)
  point P33 (218.25, 0)
  coincident P13 P26
  coincident P23 P27
  coincident P6 P28
  tangent L23 A1
  tangent A1 L24
  parallel L23 L24
  tangent L24 A2
  tangent L23 A2
  coincident L21 P34
  parallel L21 L25
  midpoint L22 P35
  midpoint L25 P35
  symmetric L1 P29 P38
  symmetric L1 P30 P36
  symmetric L1 P31 P39
  symmetric L1 P32 P42
  symmetric L1 A1 A4
  symmetric L1 A2 A3
  symmetric L1 P35 P40
  dimension "d196" distance P33 P34 = 63.5
  dimension "d197" distance L23 L24 = 3.5
extrude "Extrude5" cut sketch "Sketch3" profile of L21 L22 L23 A1 L24 A2 A3 L26 A4 L28 along normal blind 6.35
circular_pattern "C-Pattern1" TotalAngle 360
work_plane "WorkPlane2"
sketch "Sketch4" plane through (0, 0, 0) normal (0.8738, 0, -0.4862) x axis (-0.4862, 0, -0.8738)
  line L1 (-90.4875, 527.556) -> (90.4875, 527.556)
  line L2 (-90.4875, 476.756) -> (90.4875, 476.756)
  line L3 (-88.9, 476.756) -> (88.9, 476.756)
  line L4 (-88.9, 44.956) -> (88.9, 44.956)
  line L5 (-110.8231, 365.95) -> (-110.8231, 302.45)
  curve K1 (-107.792, 365.95) -> (-110.8231, 365.95)
  line L6 (-107.792, 302.45) -> (-107.792, 365.95)
  curve K2 (-110.8231, 302.45) -> (-107.792, 302.45)
  line L7 (-107.792, 365.95) -> (-107.792, 302.45)
  curve K3 (-110.8231, 365.95) -> (-107.792, 365.95)
  line L8 (-110.8231, 302.45) -> (-110.8231, 365.95)
  curve K4 (-107.792, 302.45) -> (-110.8231, 302.45)
  line L9 (-89.0127, 365.95) -> (-89.0127, 302.45)
  curve K5 (-88.9, 367.7) -> (-89.0127, 365.95)
  line L10 (-89.0127, 302.45) -> (-89.0127, 365.95)
  curve K6 (-88.9, 300.7) -> (-89.0127, 302.45)
  line L11 (-116.1852, 260.35) -> (-107.4643, 260.35)
  line L12 (-107.4643, 268.35) -> (-107.4643, 260.35)
  line L13 (-107.4643, 268.35) -> (-88.9, 268.35)
  line L14 (-107.4643, 268.35) -> (-88.9, 268.35)
  line L15 (-107.4643, 260.35) -> (-107.4643, 268.35)
  line L16 (-102.5426, 400.05) -> (-102.5426, 450.85)
  line L17 (-88.9, 400.05) -> (-102.5426, 400.05)
  line L18 (-88.9, 400.05) -> (-102.5426, 400.05)
  line L19 (-102.5426, 450.85) -> (-102.5426, 400.05)
  line L20 (-116.1852, 450.85) -> (-102.5426, 450.85)
  line L21 (-102.5426, 450.85) -> (-87.847, 450.85)
  line L22 (-102.5426, 400.05) -> (-102.5426, 450.85)
  line L23 (-87.847, 400.05) -> (-102.5426, 400.05)
  line L24 (-87.847, 450.85) -> (-87.847, 400.05)
  line L25 (-109.307, 302.45) -> (-109.307, 365.95)
  curve K7 (-106.2759, 302.45) -> (-109.307, 302.45)
  line L26 (-106.2759, 365.95) -> (-106.2759, 302.45)
  curve K8 (-109.307, 365.95) -> (-106.2759, 365.95)
  line L27 (-106.2759, 302.45) -> (-106.2759, 365.95)
  curve K9 (-109.307, 302.45) -> (-106.2759, 302.45)
  line L28 (-109.307, 365.95) -> (-109.307, 302.45)
  curve K10 (-106.2759, 365.95) -> (-109.307, 365.95)
  line L29 (-92.0449, 302.45) -> (-92.0449, 365.95)
  curve K11 (-91.9, 300.7) -> (-92.0449, 302.45)
  line L30 (-92.0449, 365.95) -> (-92.0449, 302.45)
  curve K12 (-91.9, 367.7) -> (-92.0449, 365.95)
  line L31 (-91.9, 260.35) -> (-113.1852, 260.35)
  line L32 (-91.9, 450.85) -> (-113.1852, 450.85)
  line L33 (-88.9, 451.356) -> (-108.8926, 451.356)
  line L34 (-88.9, 476.756) -> (-88.9, 451.356)
  line L35 (-108.8926, 476.756) -> (-88.9, 476.756)
  line L36 (-108.8926, 451.356) -> (-108.8926, 476.756)
  line L37 (-88.9, 438.8583) -> (-88.9, 476.756)
  line L38 (-101.6, 476.756) -> (-108.4186, 460.1134)
  circle C1 centre (-102.5426, 457.706) radius 6.35
  circle C2 centre (-102.5426, 457.706) radius 2.3813
  point P7 (-88.9, 476.756)
  point P48 (-88.9, 476.756)
  point P46 (-88.9, 476.756)
  point P5 (-90.4875, 476.756)
  point P43 (-102.5426, 457.706)
  point P50 (-108.4186, 460.1134)
  point P51 (-101.6, 476.756)
  point P40 (-113.1852, 450.85)
  point P41 (-91.9, 450.85)
  point P25 (-116.1852, 450.85)
  point P44 (-108.8926, 451.356)
  point P47 (-108.8926, 476.756)
  concentric C1 C2
  horizontal L33
  vertical L34
  horizontal L35
  vertical L36
  tangent C1 L36
  tangent C1 L33
  coincident P7 P48
  perpendicular L2 L37
  coincident P46 L37
  coincident P5 L35
  coincident L19 P43
  coincident C1 P50
  coincident L35 P51
  tangent C1 L38
  dimension "d208" distance P40 P41 = 21.2852
  dimension "d209" diameter C1 = 12.7
  dimension "d210" diameter C2 = 4.7625 (= "( 3 / 16 ) * 1 in")
  dimension "d211" distance P5 P25 = 25.906
  dimension "d212" distance P44 P47 = 25.4
  dimension "d213" distance L37 P51 = 12.7
place_component sketch "Sketch4"
face "Face1" sketch "Sketch4"
remove_instance "RemoveInstance1"
sketch "Sketch7" plane through (0, 0, 49.403) normal (0, 0, -1) x axis (1, 0, 0)
  line L1 (-13.7445, 62.1652) -> (-13.7445, 56.8027)
  line L2 (-2.9845, 62.1652) -> (-13.7445, 62.1652)
  line L3 (-2.9845, 56.8027) -> (-2.9845, 62.1652)
  line L4 (-13.7445, 56.8027) -> (-2.9845, 56.8027)
  line L5 (11.5907, 31.4675) -> (16.9532, 31.4675)
  line L6 (11.5907, 42.2275) -> (11.5907, 31.4675)
  line L7 (16.9532, 42.2275) -> (11.5907, 42.2275)
  line L8 (16.9532, 31.4675) -> (16.9532, 42.2275)
  line L9 (-3.729, 50.0924) -> (-3.729, 40.3316)
  line L10 (3.729, 40.3316) -> (3.729, 50.0924)
  line L11 (-47.4613, 45.212) -> (0, 45.212)
  line L12 (-40.4812, 45.212) -> (-34.4812, 45.212)
  line L13 (-24.246, 77.629) -> (-32.0572, 57.912)
  line L14 (-15.6338, 64.4956) -> (0, 45.212)
  arc A1 centre (0, 45.212) radius 6.142 clockwise from (-3.729, 50.0924) to (3.729, 50.0924)
  arc A2 centre (0, 45.212) radius 6.142 clockwise from (3.729, 40.3316) to (-3.729, 40.3316)
  circle C1 centre (0, 45.212) radius 40.4812
  circle C2 centre (0, 45.212) radius 34.4812
  circle C3 centre (0, 45.212) radius 24.8248
  circle C4 centre (-13.1559, 72.5305) radius 1.61
  circle C5 centre (0, 14.8908) radius 1.61
  circle C6 centre (13.1559, 72.5305) radius 1.61
  circle C7 centre (-29.561, 51.9591) radius 1.61
  circle C8 centre (23.7061, 26.307) radius 1.61
  circle C9 centre (29.561, 51.9591) radius 1.61
  circle C10 centre (-23.7061, 26.307) radius 1.61
  circle C11 centre (0, 45.212) radius 20.1612
  circle C12 centre (0, 45.212) radius 40.4812
  circle C13 centre (0, 14.8908) radius 1.61
  circle C14 centre (-29.561, 51.9591) radius 1.61
  circle C15 centre (13.1559, 72.5305) radius 1.61
  circle C16 centre (29.561, 51.9591) radius 1.61
  circle C17 centre (-13.1559, 72.5305) radius 1.61
  circle C18 centre (-23.7061, 26.307) radius 1.61
  circle C19 centre (23.7061, 26.307) radius 1.61
  point P13 (0, 45.212)
  point P15 (0, 45.212)
  point P18 (-34.4812, 45.212)
  point P19 (-40.4812, 45.212)
  point P20 (-32.0572, 57.912)
  point P21 (-24.246, 77.629)
  point P22 (0, 45.212)
  point P3 (-13.7445, 62.1652)
  point P23 (-13.7445, 62.1652)
  point P24 (0, 45.212)
  point P25 (-15.6338, 64.4956)
  coincident P13 P15
  perpendicular L10 L11
  coincident C2 P18
  coincident L11 P18
  coincident C1 P19
  coincident L11 P19
  coincident C2 P20
  coincident C1 P21
  tangent C2 L13
  coincident P15 P22
  coincident P3 P23
  coincident P22 P24
  coincident C3 P25
  coincident P23 L14
  dimension "d202" = -6
  dimension "d203" distance L11 P20 = 12.7
  dimension "d204" distance P3 P25 = 3
face "Face1" sketch "Sketch7"
as_built_joint "As-built3"
sketch "Sketch60" plane through (0, 0, 43.053) normal (0, 0, -1) x axis (1, 0, 0)
  line L1 (-40.4812, 68.326) -> (-34.4812, 68.326)
  line L2 (-32.0572, 81.026) -> (-24.246, 100.743)
  line L3 (0, 68.326) -> (-13.1559, 95.6445)
  circle C1 centre (13.1559, 95.6445) radius 1.61
  circle C2 centre (-29.561, 75.0731) radius 1.61
  circle C3 centre (29.561, 75.0731) radius 1.61
  circle C4 centre (23.7061, 49.421) radius 1.61
  circle C5 centre (-13.1559, 95.6445) radius 1.61
  circle C6 centre (0, 68.326) radius 24.8248
  circle C7 centre (-23.7061, 49.421) radius 1.61
  circle C8 centre (0, 38.0048) radius 1.61
  arc A1 centre (0, 68.326) radius 34.4813 clockwise from (-34.4812, 68.326) to (-32.0572, 81.026)
  arc A2 centre (0, 68.326) radius 40.4812 clockwise from (-24.246, 100.743) to (-40.4812, 68.326)
  circle C9 centre (-13.1559, 95.6445) radius 3
  circle C10 centre (0, 68.326) radius 27.3212
  circle C11 centre (0, 68.326) radius 28.3213
  arc A3 centre (-7.1957, 100.6177) radius 4.7625 clockwise from (-6.1599, 95.9692) to (-10.8525, 97.5665)
  arc A4 centre (-20.7602, 94.0854) radius 4.7625 clockwise from (-16.0948, 95.042) to (-17.7717, 90.3773)
  arc A5 centre (-33.0833, 68.1557) radius 4.7625 clockwise from (-30.9223, 72.3997) to (-28.3209, 68.1803)
  circle C12 centre (-29.561, 75.0731) radius 3
  arc A6 centre (-29.7332, 82.8337) radius 4.7625 clockwise from (-25.453, 80.7453) to (-29.6276, 78.0724)
  arc A7 centre (-20.494, 42.3543) radius 4.7625 clockwise from (-22.4647, 46.6899) to (-17.5438, 46.093)
  circle C13 centre (-23.7061, 49.421) radius 3
  arc A8 centre (-29.8809, 54.1251) radius 4.7625 clockwise from (-25.5795, 56.1693) to (-26.0925, 51.239)
  arc A9 centre (7.5277, 36.11) radius 4.7625 clockwise from (2.9093, 37.2725) to (6.4441, 40.7476)
  circle C14 centre (0, 38.0048) radius 3
  arc A10 centre (-7.5277, 36.11) radius 4.7625 clockwise from (-6.4441, 40.7476) to (-2.9093, 37.2725)
  arc A11 centre (29.8809, 54.1251) radius 4.7625 clockwise from (26.0925, 51.239) to (25.5795, 56.1693)
  circle C15 centre (23.7061, 49.421) radius 3
  arc A12 centre (20.494, 42.3543) radius 4.7625 clockwise from (17.5438, 46.093) to (22.4647, 46.6899)
  arc A13 centre (29.7332, 82.8337) radius 4.7625 clockwise from (29.6276, 78.0724) to (25.453, 80.7453)
  circle C16 centre (29.561, 75.0731) radius 3
  arc A14 centre (33.0833, 68.1557) radius 4.7625 clockwise from (28.3209, 68.1803) to (30.9223, 72.3997)
  arc A15 centre (7.1957, 100.6177) radius 4.7625 clockwise from (10.8525, 97.5665) to (6.1599, 95.9692)
  circle C17 centre (13.1559, 95.6445) radius 3
  arc A16 centre (20.7602, 94.0854) radius 4.7625 clockwise from (17.7717, 90.3773) to (16.0948, 95.042)
  point P15 (-11.8542, 92.9416)
  point P14 (-13.1559, 95.6445)
  point P16 (-13.1559, 95.6445)
  point P7 (0, 68.326)
  point P17 (0, 68.326)
  point P21 (-6.1599, 95.9692)
  point P20 (-10.8525, 97.5665)
  point P24 (-16.0948, 95.042)
  point P25 (-17.7717, 90.3773)
  concentric C5 C9
  coincident C9 P15
  coincident P14 P16
  coincident P7 P17
  coincident P15 L3
  concentric C6 C10
  coincident P15 C10
  tangent C11 A3
  coincident C11 P21
  coincident C9 P20
  tangent C9 A3
  symmetric L3 P20 P24
  symmetric L3 P21 P25
  symmetric L3 A3 A4
  dimension "d727" diameter C9 = 6
  dimension "d728" = 1
  dimension "d729" radius A3 = 4.7625 (= "( 3 / 16 ) * 1 in")
  dimension "d731" C-Pattern1-Angle = 360
extrude "Extrude1" cut sketch "Sketch60" profile of C6 C9 C10 C11 C12 C13 C14 C15 C16 C17 against normal blind 6.35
